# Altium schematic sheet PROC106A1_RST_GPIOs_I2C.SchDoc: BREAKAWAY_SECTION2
size 431 x 279 mm; Date: Not shown in title block; ApprovedBy: Not shown in title block; CheckedBy: Not shown in title block; Author: Not shown in title block; CompanyName: Not shown in title block; DrawnBy: Antony/Anand Ram; Engineer: Not shown in title block; Organization: Not shown in title block; Address1: Not shown in title block; Address2: Not shown in title block; Address3: Not shown in title block; Address4: Not shown in title block; DocumentNumber: 8; Revision: Use project parameter SCH_Rev; SheetNumber: 8; SheetTotal: 12; PageSetup: Record=PageOptions¦CenterHorizontal=True¦CenterVertical=True¦PrintScale=1.00¦XCorrection=1.00¦YCorrection=1.00¦PrintKind=0¦BorderSize=5000000¦LeftOffset=0¦BottomOffset=0¦Orientation=2¦PaperLength=1000¦PaperWidth=1000¦Scale=100¦PaperSource=15¦PrintQuality=600¦MediaType=1¦DitherType=10¦PaperKind=Letter¦PrintScaleMode=1
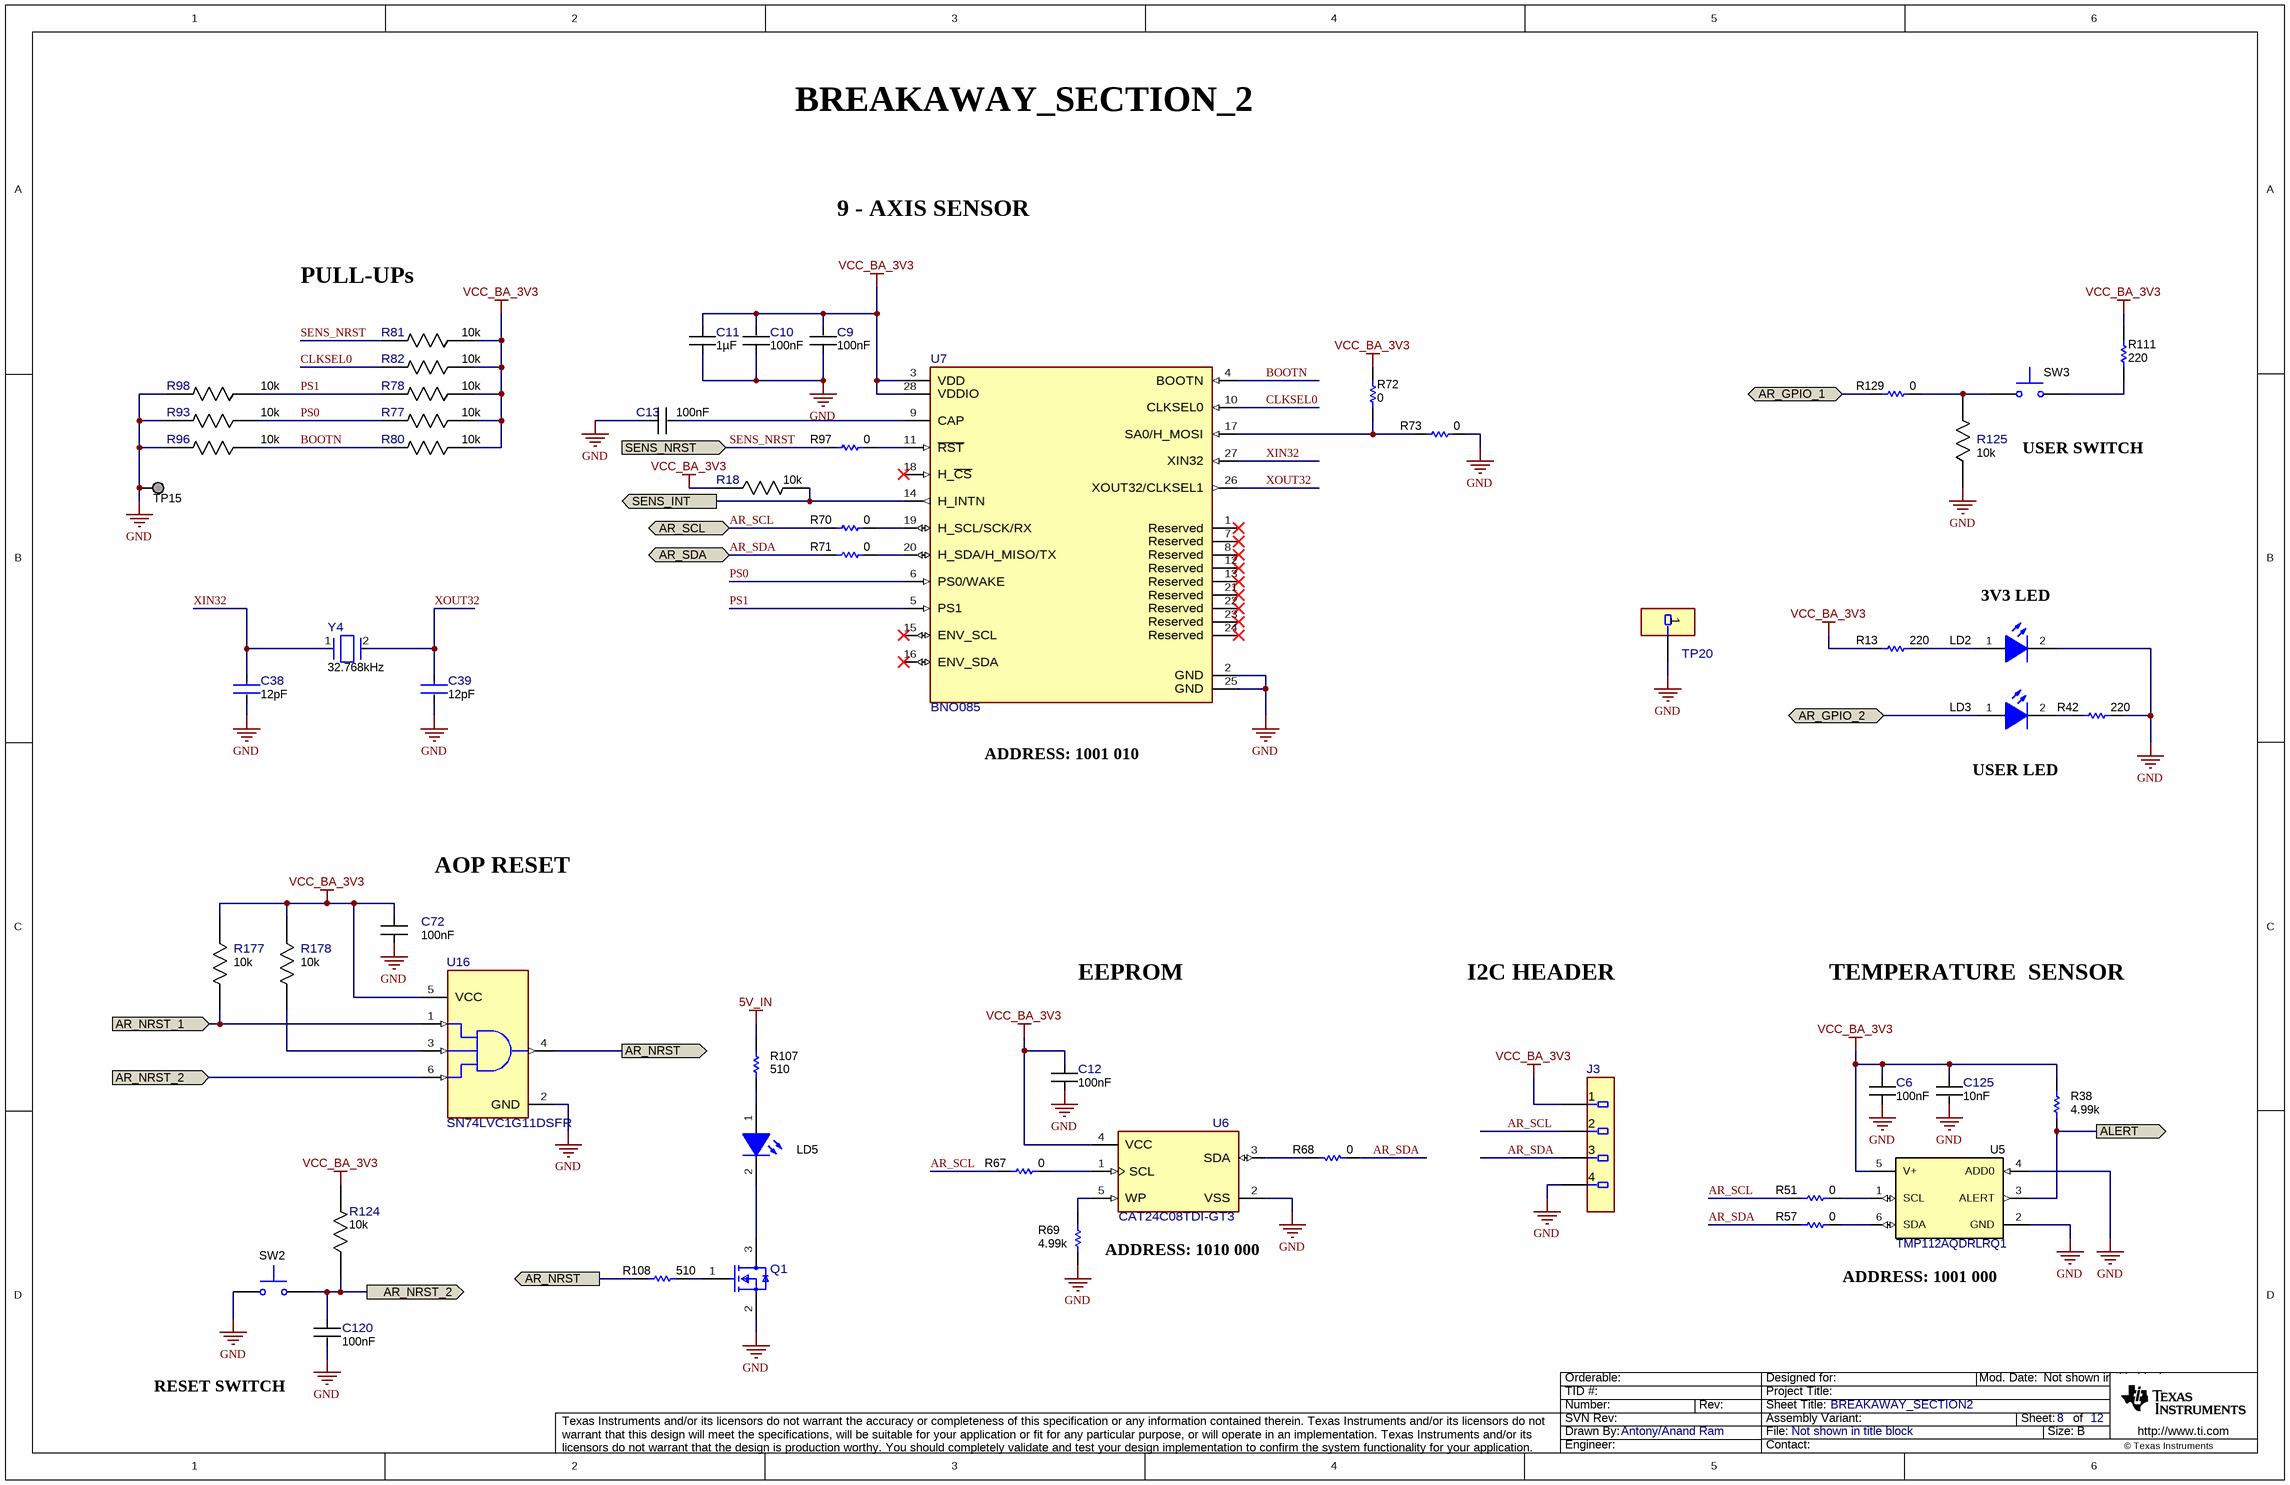
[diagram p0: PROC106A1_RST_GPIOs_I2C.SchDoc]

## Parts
C6  Cap_F: 100nF  [FP-GRM033R6YA104KE14D_0201 (0603 Metric)-IPC_C]  (hidden comment: GRM033R6YA104KE14D)
C9  Cap_F: 100nF  [FP-GRM033R6YA104KE14D_0201 (0603 Metric)-IPC_C]  (hidden comment: GRM033R6YA104KE14D)
C10  Cap_F: 100nF  [FP-GRM033R6YA104KE14D_0201 (0603 Metric)-IPC_C]  (hidden comment: GRM033R6YA104KE14D)
C11  Cap_F: 1µF  [FP-CL03A105MO3NRNH_0201-IPC_C]  (hidden comment: CL03A105MO3NRNH)
C12  Cap_F: 100nF  [FP-GRM033R6YA104KE14D_0201 (0603 Metric)-IPC_C]  (hidden comment: GRM033R6YA104KE14D)
C13  Cap_F: 100nF  [FP-GRM033R6YA104KE14D_0201 (0603 Metric)-IPC_C]  (hidden comment: GRM033R6YA104KE14D)
C38  Cap_F: 12pF  [FP-250R05L120JV4T_0201-IPC_C]  (hidden comment: 250R05L120JV4T)
C39  Cap_F: 12pF  [FP-250R05L120JV4T_0201-IPC_C]  (hidden comment: 250R05L120JV4T)
C72  Cap_F: 100nF  [FP-GRM033R6YA104KE14D_0201 (0603 Metric)-IPC_C]  (hidden comment: GRM033R6YA104KE14D)
C120  Cap_F: 100nF  [FP-GRM033R6YA104KE14D_0201 (0603 Metric)-IPC_C]  (hidden comment: GRM033R6YA104KE14D)
C125  Cap_F: 10nF  [FP-CL03A103KA3NNNC_0201-IPC_C]  (hidden comment: CL03A103KA3NNNC)
J3  M50-3930442  [FP-M50-3930442_HDR4-Recommended_Land_Pattern]  (value not drawn)
LD2  APHHS1005CGCK  [APHHS1005_Green]  (value not drawn)
LD3  APHHS1005CGCK  [APHHS1005_Green]  (value not drawn)
LD5  APHHS1005CGCK  [APHHS1005_Green]  (value not drawn)
Q1  BSS123-7-F  [FP-BSS123-7-F_SOT23-IPC_C]  (value not drawn)
R13  value 220  [0201L]  (hidden comment: RC0201JR-07220RL)
R18  Res_ohm: 10k  [FP-RR0306P-103-D_0201-IPC_C]  (hidden comment: RR0306P-103-D)
R38  value 4.99k  [0201L]  (hidden comment: RC0201FR-074K99L)
R42  value 220  [0201L]  (hidden comment: RC0201JR-07220RL)
R51  Res_ohm: 0  [FP-RC0201JR-070RL_0201 (0603 Metric)-MFG]  (hidden comment: RC0201JR-070RL)
R57  Res_ohm: 0  [FP-RC0201JR-070RL_0201 (0603 Metric)-MFG]  (hidden comment: RC0201JR-070RL)
R67  Res_ohm: 0  [FP-RC0201JR-070RL_0201 (0603 Metric)-MFG]  (hidden comment: RC0201JR-070RL)
R68  Res_ohm: 0  [FP-RC0201JR-070RL_0201 (0603 Metric)-MFG]  (hidden comment: RC0201JR-070RL)
R69  value 4.99k  [0201L]  (hidden comment: RC0201FR-074K99L)
R70  Res_ohm: 0  [FP-RC0201JR-070RL_0201 (0603 Metric)-MFG]  (hidden comment: RC0201JR-070RL)
R71  Res_ohm: 0  [FP-RC0201JR-070RL_0201 (0603 Metric)-MFG]  (hidden comment: RC0201JR-070RL)
R72  Res_ohm: 0  [FP-RC0201JR-070RL_0201 (0603 Metric)-IPC_C]  (hidden comment: RC0201JR-070RL)
R73  Res_ohm: 0  [FP-RC0201JR-070RL_0201 (0603 Metric)-IPC_C]  (hidden comment: RC0201JR-070RL)
R77  Res_ohm: 10k  [FP-RR0306P-103-D_0201-IPC_C]  (hidden comment: RR0306P-103-D)
R78  Res_ohm: 10k  [FP-RR0306P-103-D_0201-IPC_C]  (hidden comment: RR0306P-103-D)
R80  Res_ohm: 10k  [FP-RR0306P-103-D_0201-IPC_C]  (hidden comment: RR0306P-103-D)
R81  Res_ohm: 10k  [FP-RR0306P-103-D_0201-IPC_C]  (hidden comment: RR0306P-103-D)
R82  Res_ohm: 10k  [FP-RR0306P-103-D_0201-IPC_C]  (hidden comment: RR0306P-103-D)
R93  Res_ohm: 10k  [FP-RR0306P-103-D_0201-IPC_C]  (hidden comment: RR0306P-103-D)
R96  Res_ohm: 10k  [FP-RR0306P-103-D_0201-IPC_C]  (hidden comment: RR0306P-103-D)
R97  Res_ohm: 0  [FP-RC0201JR-070RL_0201 (0603 Metric)-IPC_C]  (hidden comment: RC0201JR-070RL)
R98  Res_ohm: 10k  [FP-RR0306P-103-D_0201-IPC_C]  (hidden comment: RR0306P-103-D)
R107  value 510  [0201L]  (hidden comment: RC0201JR-07510RL)
R108  value 510  [0201L]  (hidden comment: RC0201JR-07510RL)
R111  value 220  [0201L]  (hidden comment: RC0201JR-07220RL)
R124  Res_ohm: 10k  [FP-RR0306P-103-D_0201-IPC_C]  (hidden comment: RR0306P-103-D)
R125  Res_ohm: 10k  [FP-RR0306P-103-D_0201-IPC_C]  (hidden comment: RR0306P-103-D)
R129  Res_ohm: 0  [FP-RC0201JR-070RL_0201 (0603 Metric)-IPC_C]  (hidden comment: RC0201JR-070RL)
R177  Res_ohm: 10k  [FP-RR0306P-103-D_0201-IPC_C]  (hidden comment: RR0306P-103-D)
R178  Res_ohm: 10k  [FP-RR0306P-103-D_0201-IPC_C]  (hidden comment: RR0306P-103-D)
SW2  B3U-1000P  [SW_B3U-1000P]  (value not drawn)
SW3  B3U-1000P  [SW_B3U-1000P]  (value not drawn)
TP15  TESTPOINT  [TP_25MIL-SMT]  (value not drawn)  (no BOM)
TP20  4953  [FP-4953_HDR1-MFG]  (value not drawn)
U5  TMP112AQDRLRQ1  [DRL0006A]
U6  CAT24C08TDI-GT3  [FP-CAT24C08TDI-GT3_TSOT-23-5-IPC_A]
U7  BNO085  [FP-BNO085_LGA28-MFG]
U16  SN74LVC1G11DSFR  [DSF0006A-MFG]
Y4  Frequency_Fixed: 32.768kHz  [FP-ABS05W-32.768KHZ-D-2-T_XTAL_SMT_1MM6_1MM0-MFG]  (hidden comment: ABS05W-32.768KHZ-D-2-T)

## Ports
ALERT (out), AR_GPIO_1 (bidir), AR_GPIO_2 (bidir), AR_NRST (out), AR_NRST_1 (in), AR_NRST_2 (in), AR_NRST_2 (out), AR_SCL (bidir), AR_SDA (bidir), SENS_INT (out), SENS_NRST (in)

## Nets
5V_IN: R107.1
GND: C6.1 C9.1 C10.1 C11.2 C12.1 C13.1 C38.2 C39.2 C72.1 C120.2 C125.2 J3.4 LD2.2(K) Q1.2(S) R42.2 R69.1 R73.1 R93.2 R96.2 R98.2 R125.1 SW2.2 TP15.1 TP20.1 U5.2(GND) U5.4(ADD0) U6.2(VSS) U7.2(GND) U7.25(GND) U16.2(GND)
VCC_BA_3V3: C6.2 C9.2 C10.2 C11.1 C12.2 C72.2 C125.1 J3.1 R13.1 R18.1 R38.2 R72.1 R77.1 R78.1 R80.1 R81.1 R82.1 R111.2 R124.2 R177.1 R178.1 U5.5(V+) U6.4(VCC) U7.3(VDD) U7.28(VDDIO) U16.5(VCC)
ALERT: R38.1 U5.3(ALERT) ; port ALERT
AR_GPIO_1: R129.2 ; port AR_GPIO_1
AR_GPIO_2: LD3.1(A) ; port AR_GPIO_2
AR_NRST: R108.1 U16.4(Y) ; port AR_NRST
AR_NRST_1: R177.2 U16.1(A) ; port AR_NRST_1
AR_NRST_2: C120.1 R124.1 SW2.1 U16.6(C) ; port AR_NRST_2
AR_SCL: J3.2 R51.1 R67.1 R70.2 ; port AR_SCL
AR_SDA: J3.3 R57.1 R68.1 R71.2 ; port AR_SDA
BOOTN: R80.2 R96.1 U7.4(BOOTN)
CLKSEL0: R82.2 U7.10(CLKSEL0)
PS0: R77.2 R93.1 U7.6(PS0/WAKE)
PS1: R78.2 R98.1 U7.5(PS1)
SENS_INT: R18.2 U7.14(H_INTN) ; port SENS_INT
SENS_NRST: R81.2 R97.2 ; port SENS_NRST
XIN32: C38.1 U7.27(XIN32) Y4.1
XOUT32: C39.1 U7.26(XOUT32/CLKSEL1) Y4.2
NetC13_2: C13.2 U7.9(CAP)
NetLD2_1: LD2.1(A) R13.2
NetLD3_2: LD3.2(K) R42.1
NetLD5_1: LD5.1(A) R107.2
NetLD5_2: LD5.2(K) Q1.3(D)
NetQ1_1: Q1.1(G) R108.2
NetR51_2: R51.2 U5.1(SCL)
NetR57_2: R57.2 U5.6(SDA)
NetR67_2: R67.2 U6.1(SCL)
NetR68_2: R68.2 U6.3(SDA)
NetR69_2: R69.2 U6.5(WP)
NetR70_1: R70.1 U7.19(H_SCL/SCK/RX)
NetR71_1: R71.1 U7.20(H_SDA/H_MISO/TX)
NetR72_2: R72.2 R73.2 U7.17(SA0/H_MOSI)
NetR97_1: R97.1 U7.11(~{RST})
NetR111_1: R111.1 SW3.2
NetR125_2: R125.2 R129.1 SW3.1
NetR178_2: R178.2 U16.3(B)

Not connected (* = marked no-connect by the designer): U7 1(Reserved)* 7(Reserved)* 8(Reserved)* 12(Reserved)* 13(Reserved)* 15(ENV_SCL)* 16(ENV_SDA)* 18(H_~{CS})* 21(Reserved)* 22(Reserved)* 23(Reserved)* 24(Reserved)*

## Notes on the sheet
- BREAKAWAY_SECTION_2
- 9 - AXIS SENSOR
- PULL-UPs
- (near SW3) USER SWITCH
- (near LD2) 3V3 LED
- ADDRESS: 1001 010
- USER LED
- AOP RESET
- EEPROM
- I2C HEADER
- TEMPERATURE  SENSOR
- ADDRESS: 1010 000
- ADDRESS: 1001 000
- RESET SWITCH

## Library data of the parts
C6 C9 C10 C12 C13 C72 C120 = CMP-0086440-1: Cap Ceramic 0.1uF 35V X5R 10% Pad SMD 0201 85C T/R; Manufacturer: Murata Electronics North America; AEC Qualified: No; SizeZ_mm: 0.33mm; Symbol Name: SYM-GRM033R6YA104KE14D; TempCo: 15%
C11 = CMP-0086446-1: 1µF ±20% 16V Ceramic Capacitor X5R 0201; Manufacturer: Samsung Electro-Mechanics; AEC Qualified: No; SizeZ_mm: 0.39mm; Symbol Name: SYM-CL03A105MO3NRNH; TempCo: 15%
C38 C39 = CMP-0087190-1: CAP CER 12PF 25V C0G/NP0 0201; Manufacturer: Johanson Technology Inc.; AEC Grade: Grade 1; AEC Qualified: Yes; SizeZ_mm: 0.33mm; Symbol Name: SYM-250R05L120JV4T; TempCo: 30ppm/°C; Tolerance_%: 5%
C125 = CMP-0086445-1: CAP CER 10000PF 25V X5R 0201; Manufacturer: Samsung Electro-Mechanics America, Inc; AEC Qualified: No; SizeZ_mm: 0.33mm; Symbol Name: SYM-CL03A103KA3NNNC; TempCo: 15%; Tolerance_%: 10%
J3 = CMP-0087187-1: CONN HDR 1.27MM R/A AU 4POS; Manufacturer: Harwin Inc.; ContactFinish: Gold; Current_A: 1A; Row_Count: 1
LD2 LD3 LD5 = CMP-0067682-2: LED, Green, SMD; Manufacturer: Kingbright; Angle: 120.0; Power_TotalModule: 75mW; SizeZ_mm: 0.6; Vf_V: 2.1V; Vr_V: 5V; Io_A: 20mA; Ir_A: 10µA; SizeArea_mm2: 0.5; SizeAreaWB_mm2: 3.0; SizeX_mm: 1.0; Tjmax_C: 85°C; Value1: 0.075W
Q1 = CMP-0087176-1: MOSFET N-CH 100V 170MA SOT23-3; Manufacturer: Diodes Incorporated; AEC Qualified: No; ChMode: False; Rdson45_ohm: 6; SizeZ_mm: 1.1mm; Vgs_V: 20V
R13 R42 R111 = CMP-0027072-1: RES, 220, 5%, 0.05 W, 0201; Manufacturer: Yageo America; AEC Category: Q200; AEC Qualified: N; EIA_Code: E24; Power_W: 50mW; SizeArea_mm2: 0.18; SizeX_mm: 0.6; SizeY_mm: 0.3; SizeZ_mm: 0.26; TempCo: 200 ppm/C; U/M: EA; Value2: 0.05W; Value_Code: 220R; VDC_V: 25V
R18 R77 R78 R80-R82 R93 R96 R98 R124 R125 R177 R178 = CMP-0088002-1: 10 kOhms ±0.5% 0.05W, 1/20W Chip Resistor 0201 (0603 Metric)  Thin Film; Manufacturer: Susumu; AEC Qualified: No; Power_W: 50mW; SizeZ_mm: 0.26mm; Symbol Name: SYM-RR0306P-103-D; TempCo: 25ppm/°C; VDC_V: 15V
R38 R69 = CMP-0027745-1: RES, 4.99 k, 1%, 0.05 W, 0201; Manufacturer: Yageo America; AEC Category: Q200; AEC Qualified: N; EIA_Code: E96; Power_W: 50mW; SizeArea_mm2: 0.18; SizeX_mm: 0.6; SizeY_mm: 0.3; SizeZ_mm: 0.26; TempCo: 200 ppm/C; U/M: EA; Value2: 0.05W; Value_Code: 4k99; VDC_V: 25V
R51 R57 R67 R68 R70-R73 R97 R129 = CMP-0086442-2: RES SMD 0 OHM JUMPER 1/20W 0201; Manufacturer: Yageo; AEC Qualified: No; Power_W: 50mW; SizeZ_mm: 0.26mm; TempCo: 200ppm/°C; Tolerance_%: 5%; VDC_V: 25V
R107 R108 = CMP-0027137-1: RES, 510, 5%, 0.05 W, 0201; Manufacturer: Yageo America; AEC Category: Q200; AEC Qualified: N; EIA_Code: E24; Power_W: 50mW; SizeArea_mm2: 0.18; SizeX_mm: 0.6; SizeY_mm: 0.3; SizeZ_mm: 0.26; TempCo: 200 ppm/C; U/M: EA; Value2: 0.05W; Value_Code: 510R; VDC_V: 25V
SW2 SW3 = CMP-0002150-2: SWITCH TACTILE SPST-NO 0.05A 12V; Manufacturer: Omron Electronic Components; CurrentRating_mA: 50A; PositionCount: 1; SwitchFunction: Off-Mom
TP15 = CMP-0078143-3: TEST POINT.  No entry in BOM.
TP20 = CMP-0086474-1: PC Test Point, Loop Brass, Tin Plating 0.047" (1.19mm) Hole Diameter Mounting Type; Manufacturer: Keystone Electronics
U5 = CMP-0067398-2: Automotive Grade, 1.4V-Capable +/-0.5degC Temperature Sensor with Alert Function and I2C/SMBus, DRL0006A (SOT-OTHER-6); Alternate Manufacturer: Texas Instruments; CompType: IC; SizeArea_mm2: 2.56; SizeAreaWB_mm2: 6.76; SizeX_mm: 1.6; SizeZ_mm: 0.6; U/M: EA
U6 = CMP-0087170-1: 8KB I2C SER EEPROM TSOT 23; Manufacturer: ON Semiconductor; SizeZ_mm: 1mm
U7 = CMP-0087171-1: IMU ACCEL/GYRO/MAG I2C 32BIT; Manufacturer: Hillcrest Laboratories, Inc.; SizeZ_mm: 1.18mm
U16 = CMP-0087998-2: AND Gate IC 1 Channel  6-SON (1x1); Manufacturer: Texas Instruments; TJmax_C: +150°C; PositionCount: 1; Number Of Inputs: 3; SizeZ_mm: 0.4mm; TaMax_C: +125°C; Max Supply Voltage: 5.5V; Min Supply Voltage: 1.65V; Standoff Height: 0mm; AEC Qualified: No; TaMin_C: -40°C; AEC Category: Q200
Y4 = CMP-0088006-1: CRYSTAL 32.768KHZ 4PF SMD; Manufacturer: Abracon LLC; AEC Qualified: No; Frequency Tolerance: 20ppm; SizeZ_mm: 0.5mm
